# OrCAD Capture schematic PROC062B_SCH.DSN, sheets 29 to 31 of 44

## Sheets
29 28. MIPI 60 PIN CONNECTOR: size C; title: MIPI 60 PIN CONNECTOR
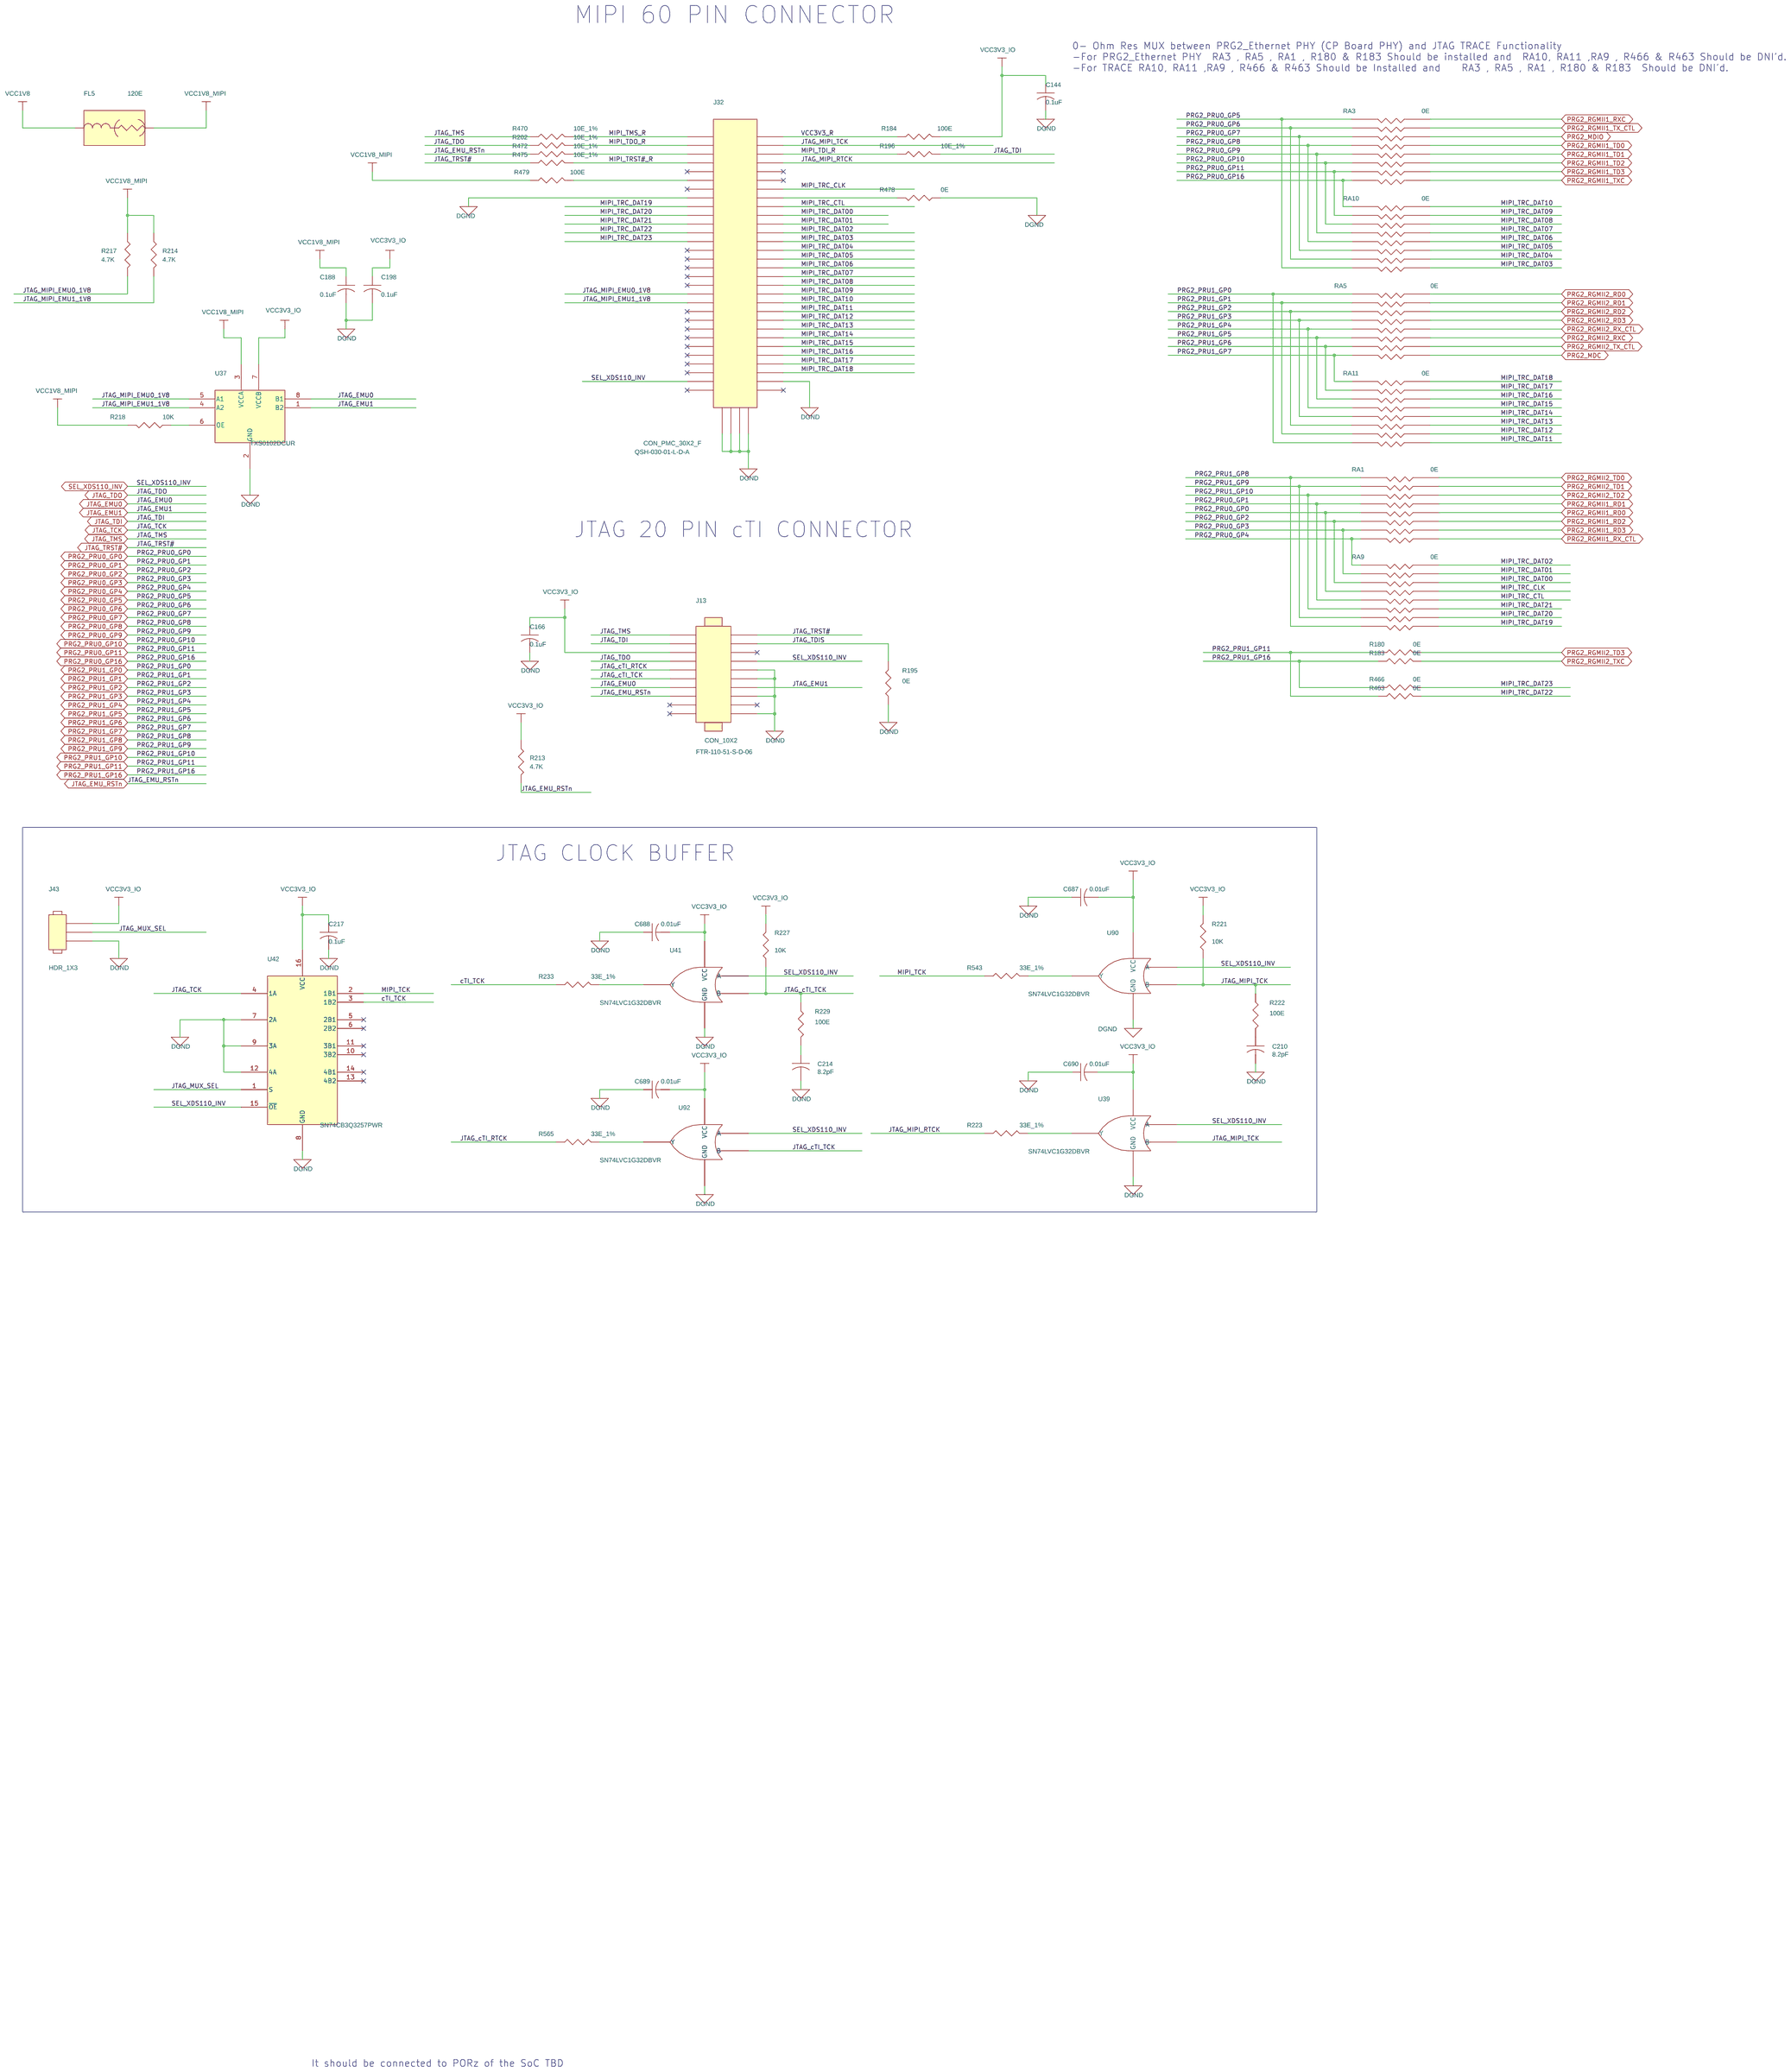
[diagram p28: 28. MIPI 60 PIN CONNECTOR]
30 29. USB2.0_INTERFACE: size C; title: USB 2.0 INTERFACE
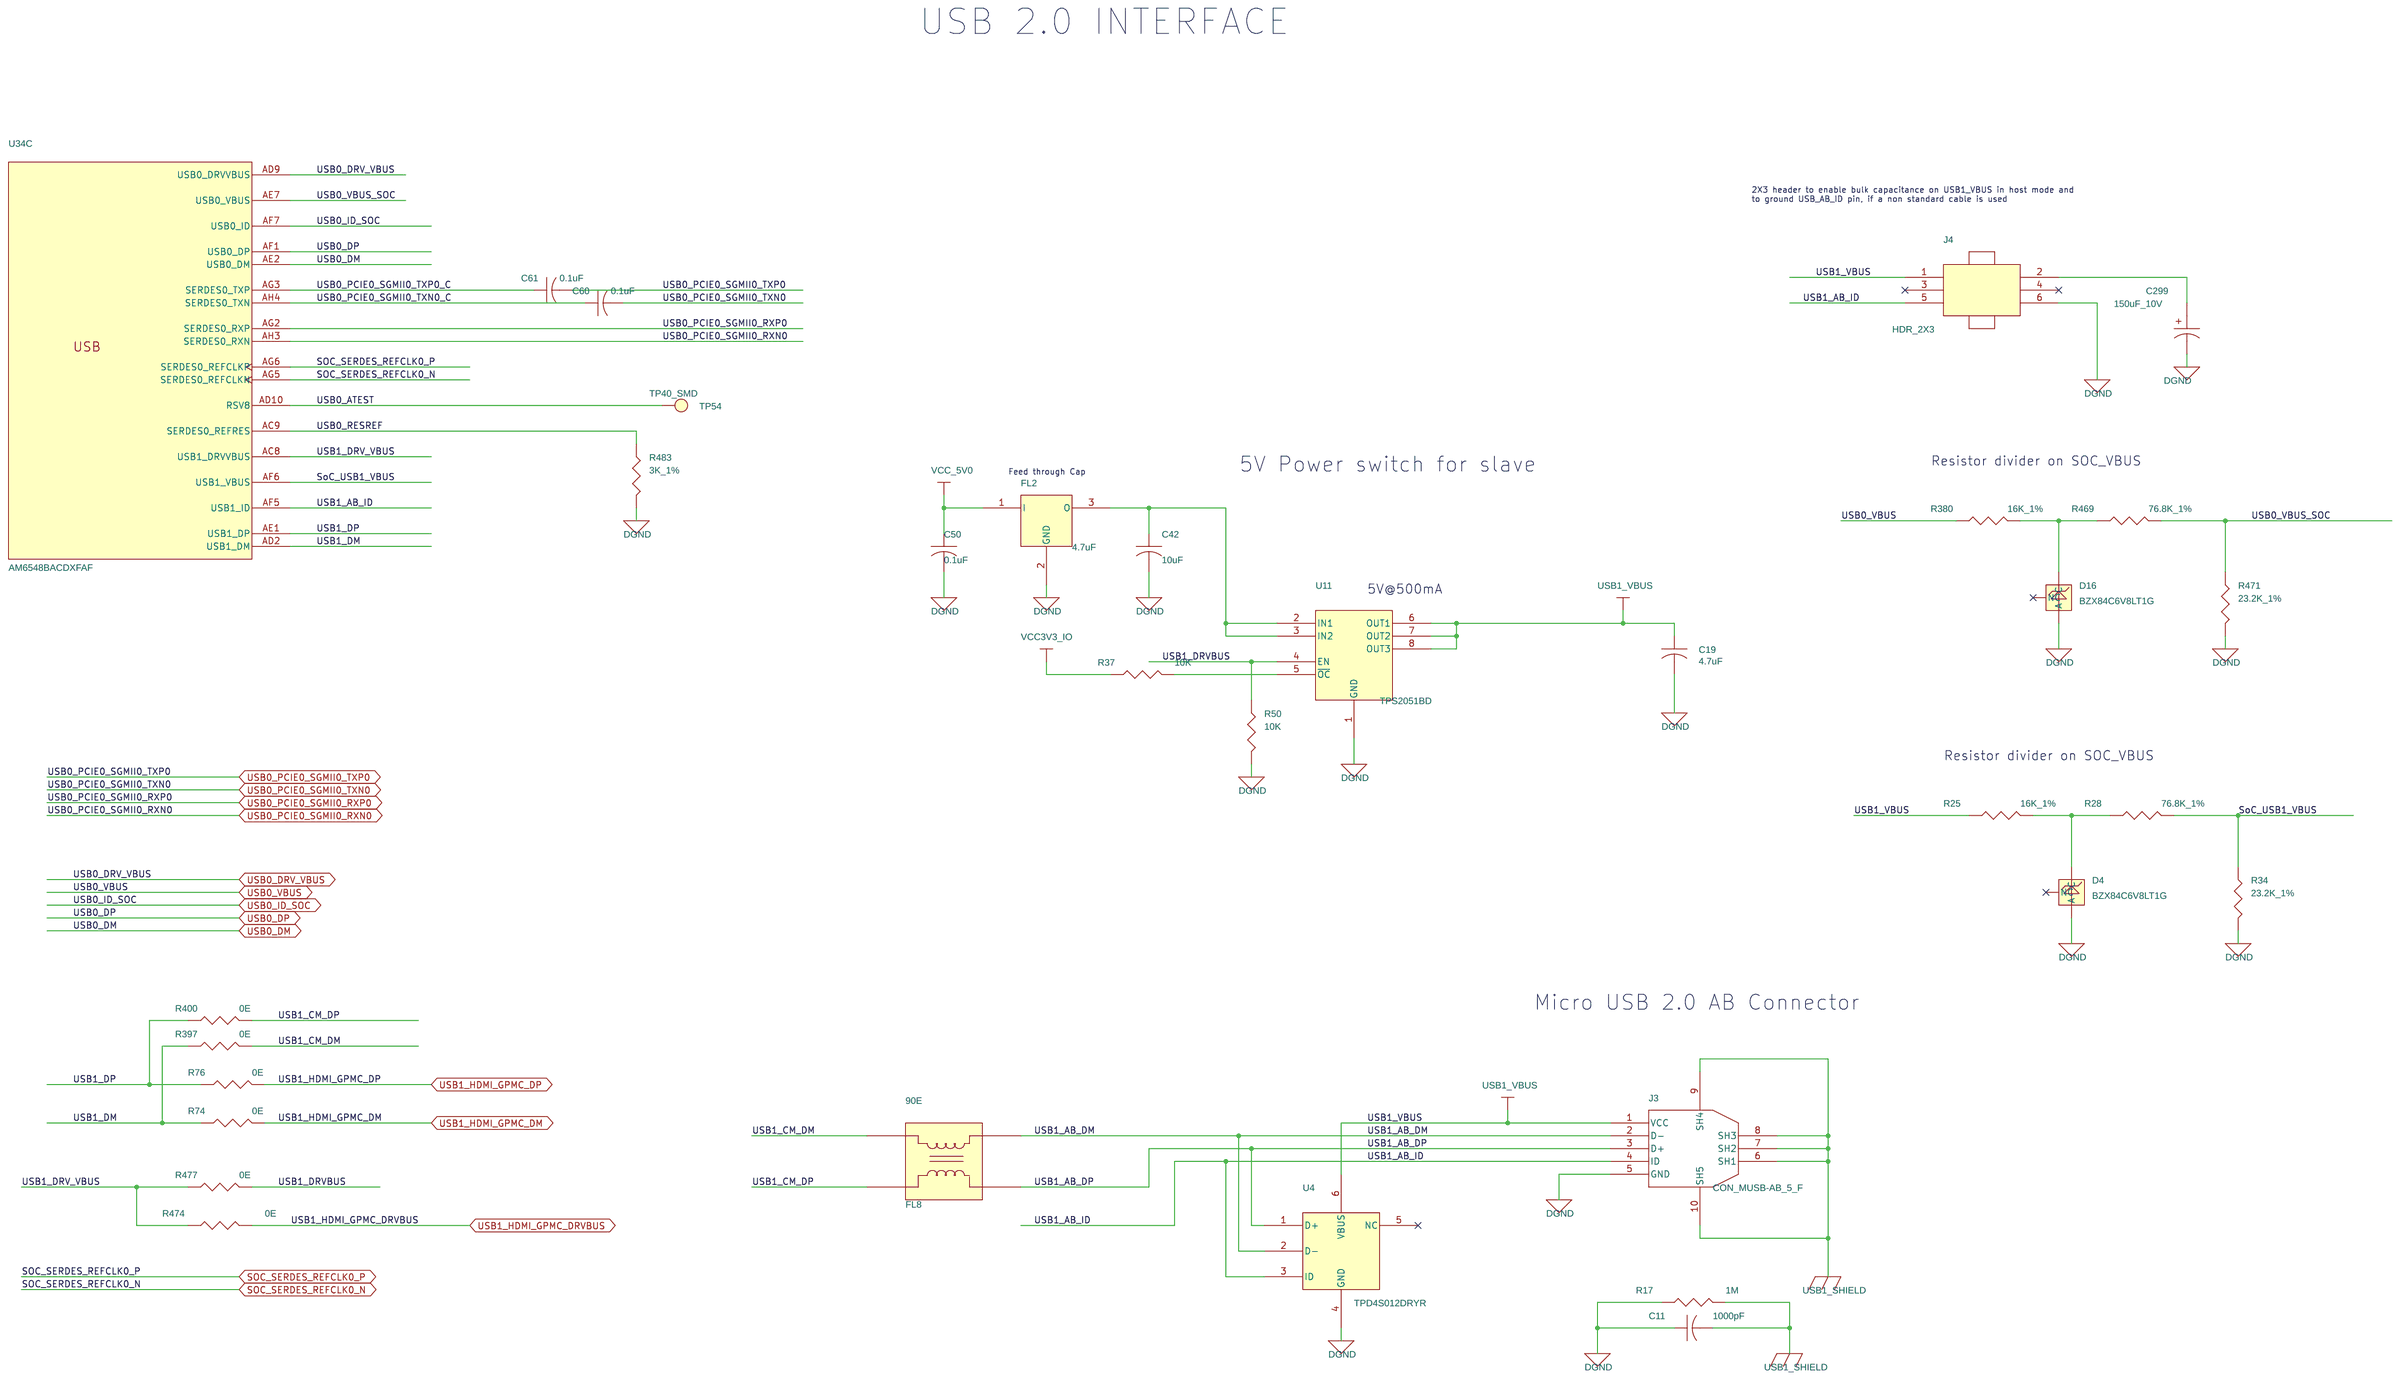
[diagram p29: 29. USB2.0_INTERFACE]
31 30. FT4232 LEVEL TRANSLATOR: size C; title: FT4232 LEVEL TRANSLATOR
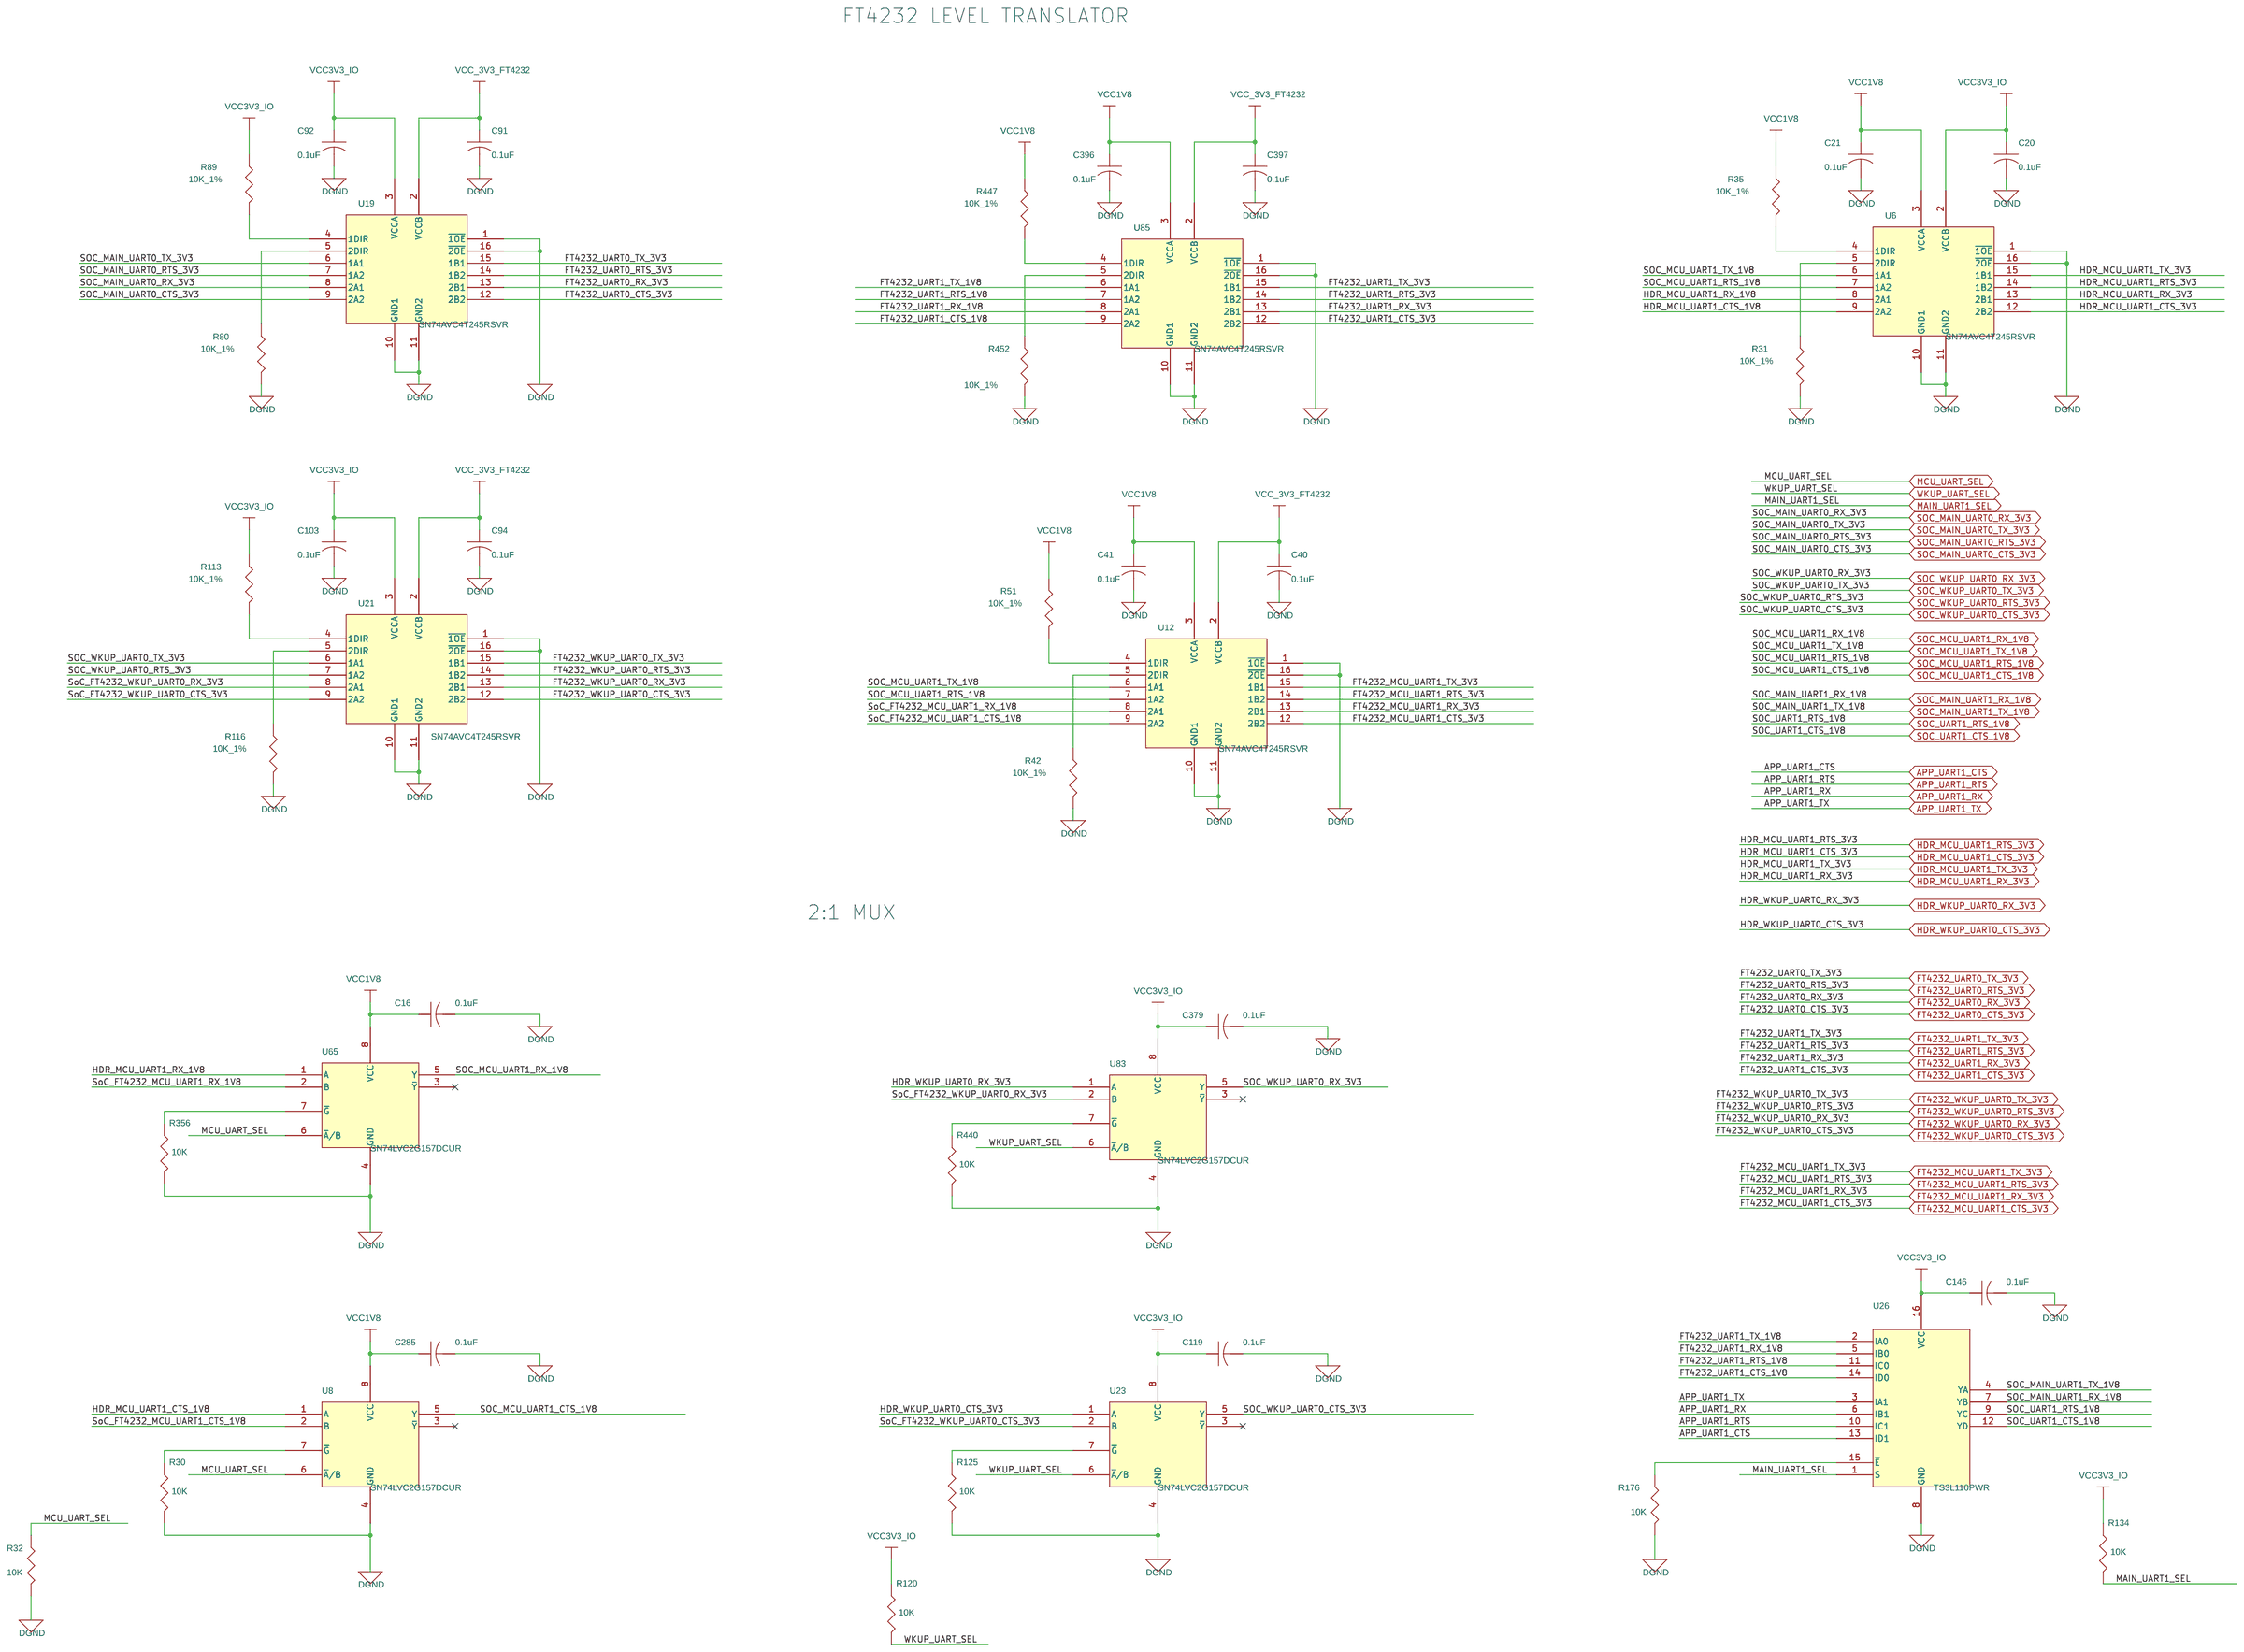
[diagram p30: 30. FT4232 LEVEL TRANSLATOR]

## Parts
sheet 16. DDR4 ECC & TERMINATIONS
U34  AM6548BACDXFAF  [BGA784_31-49_910X910_1-7]  (sections A,B,C,D,E,F,G,H,I,J,K,L,M,N,O,P,Q,R,S)
sheet 28. MIPI 60 PIN CONNECTOR
C144  0.1uF  [CAP0201_0-5]
C166  0.1uF  [CAP0201_0-5]
C188  0.1uF  [CAP0201_0-5]
C198  0.1uF  [CAP0201_0-5]
C210  8.2pF  [CAP0402_0-75]
C214  8.2pF  [CAP0402_0-75]
C217  0.1uF  [CAP0201_0-5]
C687  0.01uF  [CAP0201_0-5]
C688  0.01uF  [CAP0201_0-5]
C689  0.01uF  [CAP0201_0-5]
C690  0.01uF  [CAP0201_0-5]
FL5  120E  [EMIFIL_BLM15A_0402_0-6]
J13  CON_10X2  [CON_10X2_FTR-110-51-S-D_P_S_S]
J32  CON_PMC_30X2_F  [CON_PMC30X2_QSH-030-01-L_S_S_S]
J43  HDR_1X3  [HDR_3X1_100_S_T]
R180  0E  [RES0402_0-5]
R183  0E  [RES0402_0-5]
R184  100E  [RES0402_0-5]
R195  0E  [RES0402_0-5]
R196  10E_1%  [RES0402_0-5]
R202  10E_1%  [RES0402_0-5]
R213  4.7K  [RES0402]
R214  4.7K  [RES0402]
R217  4.7K  [RES0402]
R218  10K  [RES0402_0-5]
R221  10K  [RES0402_0-5]
R222  100E  [RES0402_0-5]
R223  33E_1%  [RES0402_0-5]
R227  10K  [RES0402_0-5]
R229  100E  [RES0402_0-5]
R233  33E_1%  [RES0402_0-5]
R463  0E  [RES0402_0-5]
R466  0E  [RES0402_0-5]
R470  10E_1%  [RES0402_0-5]
R472  10E_1%  [RES0402_0-5]
R475  10E_1%  [RES0402_0-5]
R478  0E  [RES0402_0-5]
R479  100E  [RES0402_0-5]
R543  33E_1%  [RES0402_0-5]
R565  33E_1%  [RES0402_0-5]
RA1  0E  [RESA_EXB2HV_0602-8_0-6]
RA3  0E  [RESA_EXB2HV_0602-8_0-6]
RA5  0E  [RESA_EXB2HV_0602-8_0-6]
RA9  0E  [RESA_0402-8]
RA10  0E  [RESA_0402-8]
RA11  0E  [RESA_0402-8]
U37  TXS0102DCUR  [VSSOP8_19-68_85X95_0-9]
U39  SN74LVC1G32DBVR  [SOT23-5_1-5]
U41  SN74LVC1G32DBVR  [SOT23-5_1-5]
U42  SN74CB3Q3257PWR  [TSSOP16_25-59_205X180]
U90  SN74LVC1G32DBVR  [SOT23-5_1-5]
U92  SN74LVC1G32DBVR  [SOT23-5_1-5]
sheet 29. USB2.0_INTERFACE
C11  1000pF  [CAP1206]
C19  4.7uF  [CAP0402_0-75]
C42  10uF  [CAP0603_1]
C50  0.1uF  [CAP0201_0-5]
C60  0.1uF  [CAP0402_0-75]
C61  0.1uF  [CAP0402_0-75]
C299  150uF_10V  [CAPT7343D_3-25]
D4  BZX84C6V8LT1G  [SOT23-123_1-2]
D16  BZX84C6V8LT1G  [SOT23-123_1-2]
FL2  4.7uF  [EMIFIL_NFM21P_0805_1]
FL8  90E  [IND4_ACM2012_90X50_SMD_1-3]
J3  CON_MUSB-AB_5_F  [CON_USBAB5_475900001_S_R_S_3-1]
J4  HDR_2X3  [HDR_2X3_TSW-103-07-D_S_T_8-4]
R17  1M  [RES0603_0-75]
R25  16K_1%  [RES0402]
R28  76.8K_1%  [RES0402]
R34  23.2K_1%  [RES0402]
R37  10K  [RES0402_0-5]
R50  10K  [RES0402_0-5]
R74  0E  [RES0402_0-5]
R76  0E  [RES0402_0-5]
R380  16K_1%  [RES0402]
R397  0E  [RES0402_0-5]
R400  0E  [RES0402_0-5]
R469  76.8K_1%  [RES0402]
R471  23.2K_1%  [RES0402]
R474  0E  [RES0402_0-5]
R477  0E  [RES0402_0-5]
R483  3K_1%  [RES0402_0-5]
TP54  TP40_SMD  [TP40_SMD]
U4  TPD4S012DRYR  [SON6_19-68_40X60_PB_0-6]
U11  TPS2051BD  [SOIC8_1-8]
sheet 30. FT4232 LEVEL TRANSLATOR
C16  0.1uF  [CAP0201_0-5]
C20  0.1uF  [CAP0201_0-5]
C21  0.1uF  [CAP0201_0-5]
C40  0.1uF  [CAP0201_0-5]
C41  0.1uF  [CAP0201_0-5]
C91  0.1uF  [CAP0201_0-5]
C92  0.1uF  [CAP0201_0-5]
C94  0.1uF  [CAP0201_0-5]
C103  0.1uF  [CAP0201_0-5]
C119  0.1uF  [CAP0201_0-5]
C146  0.1uF  [CAP0201_0-5]
C285  0.1uF  [CAP0201_0-5]
C379  0.1uF  [CAP0201_0-5]
C396  0.1uF  [CAP0201_0-5]
C397  0.1uF  [CAP0201_0-5]
R30  10K  [RES0402_0-5]
R31  10K_1%  [RES0402_0-5]
R32  10K  [RES0402_0-5]
R35  10K_1%  [RES0402_0-5]
R42  10K_1%  [RES0402_0-5]
R51  10K_1%  [RES0402_0-5]
R80  10K_1%  [RES0402_0-5]
R89  10K_1%  [RES0402_0-5]
R113  10K_1%  [RES0402_0-5]
R116  10K_1%  [RES0402_0-5]
R120  10K  [RES0402_0-5]
R125  10K  [RES0402_0-5]
R134  10K  [RES0402_0-5]
R176  10K  [RES0402_0-5]
R356  10K  [RES0402_0-5]
R440  10K  [RES0402_0-5]
R447  10K_1%  [RES0402_0-5]
R452  10K_1%  [RES0402_0-5]
U6  SN74AVC4T245RSVR  [UQFN16_15-74_105X75_0-6]
U8  SN74LVC2G157DCUR  [VSSOP8_19-68_85X95_0-9]
U12  SN74AVC4T245RSVR  [UQFN16_15-74_105X75_0-6]
U19  SN74AVC4T245RSVR  [UQFN16_15-74_105X75_0-6]
U21  SN74AVC4T245RSVR  [UQFN16_15-74_105X75_0-6]
U23  SN74LVC2G157DCUR  [VSSOP8_19-68_85X95_0-9]
U26  TS3L110PWR  [TSSOP16_25-59_205X180]
U65  SN74LVC2G157DCUR  [VSSOP8_19-68_85X95_0-9]
U83  SN74LVC2G157DCUR  [VSSOP8_19-68_85X95_0-9]
U85  SN74AVC4T245RSVR  [UQFN16_15-74_105X75_0-6]

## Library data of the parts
U34 = AM654X_BGA784: IC AM65X MICRO CONTROLLER UNIT BGA784; Chkd/date: ALVY/010721; Crtd /date: MANIRAJA/010721; Custom_Duty: 15%; Customs_HS_Code: 85423100; Distributor_name: NA; Distributor_part_number: NA; Footprint Path: Y:\MIS_DATABASE\Library\ALTIUM_TOOL\PCB_FOOTPRINTS\Altium_Footprint_Lib.PcbLib; Height: 1.63MM; Library Path: Y:\MIS_DATABASE\Library\ALTIUM_TOOL\SCHEMATICS_PARTS\MS_MICROCONTROLLER_Library.schlib; Mfr_name: TEXAS INSTRUMENTS; Mistral Part No: 141221070001; Package: BGA784; Part_type: ICS\DIGITAL\MICROCONTROLLER; Project: TI_AM65X_CP; RoHS: NA; Temperature: NA; Tolerance: NA; Voltage: NA; Wattage: NA; Weight: NA; Datasheet: Y:\MIS_DATABASE\DATASHEETS\ICS\DIGITAL\MICROCONTROLLER\MAXWELLM4.PDF
C16 C20 C21 C40 C41 C50 C91 C92 C94 C103 C119 C144 C146 C166 C188 C198 C217 C285 C379 C396 C397 = CAP: CAP CERAMIC 0.1uF 16V 10% X5R 0201; Chkd/date: MANIRAJA/120218; Crtd /date: MANIRAJA/120218; Custom_Duty: 15%; Customs_HS_Code: 85322990; Distributor_name: DIGIKEY; Distributor_part_number: 490-16742-1-ND; Height: 0.33MM; Mfr_name: MURATA; Mfr_part_number: GRM033R61C104KE84J; Mistral Part No: 120009030072-R; Package: 0201; Part_type: CAPACITORS\CERAMIC; Project: TI_MAXIE_CPB; RoHS: RoHS; Temperature: -55°C+85°C; Tolerance: 10%; Voltage: 16V; Wattage: NA; Weight: 0.33mg; Datasheet: Y:\MIS_DATABASE\DATASHEETS\CAPACITORS\GRM033R61C104KE84.PDF
C210 C214 = CAP: CAP CERAMIC 8.2pF 50V 0.5pF C0G(NP0) 0402; Chkd/date: MANIRAJA/240118; Crtd /date: MANIRAJA/240118; Custom_Duty: 15%; Customs_HS_Code: 85322990; Distributor_name: DIGIKEY; Distributor_part_number: GCM1555C1H8R2DA16D-ND; Height: 0.55MM; Mfr_name: MURATA; Mfr_part_number: GCM1555C1H8R2DA16D; Mistral Part No: 120018010017-R; Package: 0402; Part_type: CAPACITORS\CERAMIC; Project: TI_MAXIE_CPB; RoHS: RoHS; Temperature: -55°C+125°C; Tolerance: 0.5pF%; Voltage: 50V; Wattage: NA; Weight: 6mg; Datasheet: Y:\MIS_DATABASE\DATASHEETS\CAPACITORS\MURATA-GCM-SER.PDF
C687-C690 = CAP: CAP CERAMIC 0.01uF 25V 10% X5R 0201; Chkd/date: MANIRAJA/230118; Crtd /date: MANIRAJA/230118; Custom_Duty: 15%; Customs_HS_Code: 85322990; Distributor_name: DIGIKEY; Distributor_part_number: GRM033R61E103KA12J-ND; Height: 0.33MM; Mfr_name: MURATA; Mfr_part_number: GRM033R61E103KA12J; Mistral Part No: 120018010007-R; Package: 0201; Part_type: CAPACITORS\CERAMIC; Project: TI_MAXIE_CPB; RoHS: RoHS; Temperature: -55°C+85°C; Tolerance: 10%; Voltage: 25V; Wattage: NA; Weight: 0.33mg; Datasheet: Y:\MIS_DATABASE\DATASHEETS\CAPACITORS\GRM033R61E103KA12.PDF
FL5 = EMIFILTER_IND: FERRITE CHIP 120E 1.3A 0402; Chkd/date: VASANTHA/010117; Crtd /date: CHAITHANYA/150312; Custom_Duty: 24%; Customs_HS_Code: 85437099; Distributor_name: DIGIKEY; Distributor_part_number: 490-5203-1-ND; Footprint Path: Y:\MIS_DATABASE\Library\ALTIUM_TOOL\PCB_FOOTPRINTS\Altium_Footprint_Lib.PcbLib; Height: 0.55MM; Library Path: Y:\MIS_DATABASE\Library\ALTIUM_TOOL\SCHEMATICS_PARTS\MS_FILTER_Library.schlib; Mfr_name: MURATA; Mfr_part_number: BLM15PD121SN1; Mistral Part No: 130012030043-R; Package: 0402; Part_type: MISC\FILTER; Project: GEN_3-8; RoHS: RoHS; Temperature: -55°C+125°C; Tolerance: 25%; Voltage: NA; Wattage: NA; Weight: 0.65mg; Datasheet: Y:\MIS_DATABASE\DATASHEETS\DISCRETES\INDUCTORS\BLM18K-SERIES.PDF
J13 = CON_10X2: CON 10X2 1.27MM PITCH MALE SMD; Chkd/date: BAVISH/050911; Crtd /date: CHAITHANYA/050811; Custom_Duty: 24%; Customs_HS_Code: 85369090; Distributor_name: DIGIKEY; Distributor_part_number: FTR-110-51-S-D-06-ND; Height: 7.37MM; Mfr_name: SAMTEC; Mfr_part_number: FTR-110-51-S-D-06; Mistral Part No: 150011090001-R; Package: SMD; Part_type: CONNECTOR\MISCELLANEOUS; Project: GEMYC; RoHS: RoHS; Temperature: -55°C+105°C; Tolerance: NA; Voltage: NA; Wattage: NA; Weight: NA; Datasheet: Y:\MIS_DATABASE\DATASHEETS\CONNECTORS\FTR-SERIES1.PDF
J32 = CON_PMC_30X2_F: CON PMC 30X2 0.50MM PITCH FEMALE ST SMD; Chkd/date: MAZHAR/180208; Crtd /date: USMAN/051108; Custom_Duty: 24%; Customs_HS_Code: 85369090; Height: 3.25MM; Mfr_name: SAMTEC; Mfr_part_number: QSH-030-01-L-D-A; Mistral Part No: 150009030606; Package: SMD; Part_type: CONNECTOR\PMC; Project: KHAN_HSST; Datasheet: Y:\MIS_DATABASE\DATASHEETS\CONNECTORS\QSH.PDF
J43 = HEADER_3X1: HDR 1X3 2.54MM PITCH ST TH; Chkd/date: VASANTHA/290616; Crtd /date: VASANTHA/290616; Custom_Duty: 15%; Customs_HS_Code: 85322990; Distributor_name: DIGIKEY; Distributor_part_number: 609-3471-ND; Height: 8.58MM; Mfr_name: FCI; Mfr_part_number: 68001-403HLF; Mistral Part No: 150016060025-R; Package: THRU-HOLE; Part_type: CONNECTOR\HEADERS; Project: IKEYP; RoHS: RoHS; Temperature: -40°C+105°C; Tolerance: NA; Voltage: NA; Wattage: NA; Weight: NA; Datasheet: Y:\MIS_DATABASE\DATASHEETS\CONNECTORS\68000.PDF
R180 R183 R463 R466 = RESISTOR: RES 0E 1/16W 0402; Chkd/date: VASANTHA/201216; Crtd /date: MUDDU/190810; Custom_Duty: 15%; Customs_HS_Code: 85332119; Distributor_name: DIGIKEY; Distributor_part_number: 541-0.0JCT-ND; Footprint Path: Y:\MIS_DATABASE\Library\ALTIUM_TOOL\PCB_FOOTPRINTS\Altium_Footprint_Lib.PcbLib; Height: 0.40MM; Library Path: Y:\MIS_DATABASE\Library\ALTIUM_TOOL\SCHEMATICS_PARTS\MS_DISCRETE_Library.schlib; Mfr_name: VISHAY; Mfr_part_number: CRCW04020000Z0ED; Mistral Part No: 110010080019-P; Package: 0402; Part_type: RESISTORS\FIXED; Project: PB_BUGBASE; RoHS: Pb-Free; SIGNAL_MODEL: RES; Temperature: -55°C+155°C; Tolerance: NA; Voltage: NA; Wattage: 1/16W; Weight: 0.65g/1000pcs; Datasheet: Y:\MIS_DATABASE\DATASHEETS\RESISTORS\CRCW0603.PDF
R184 R222 R229 R479 = RESISTOR: RES 100E 1/16W 5% 0402; Chkd/date: MANIRAJA/230817; Crtd /date: MANIRAJA/230817; Custom_Duty: 15%; Customs_HS_Code: 85332119; Distributor_name: DIGIKEY; Distributor_part_number: 541-100JCT-ND; Height: 0.40MM; Mfr_name: VISHAY; Mfr_part_number: CRCW0402100RJNED; Mistral Part No: 110009030164-R; Package: 0402; Part_type: RESISTORS\FIXED; Project: TI_MAXIE_CPB; RoHS: RoHS; Temperature: -55°C+155°C; Tolerance: 5%; Voltage: NA; Wattage: 1/16W; Weight: 0.65mg; Datasheet: Y:\MIS_DATABASE\DATASHEETS\RESISTORS\CRCW0603.PDF
R74 R76 R195 R397 R400 R474 R477 R478 = RESISTOR: RES 0E 1/16W 0402; Chkd/date: VASANTHA/201216; Crtd /date: MUDDU/190810; Custom_Duty: 15%; Customs_HS_Code: 85332119; Distributor_name: DIGIKEY; Distributor_part_number: 541-0.0JCT-ND; Footprint Path: Y:\MIS_DATABASE\Library\ALTIUM_TOOL\PCB_FOOTPRINTS\Altium_Footprint_Lib.PcbLib; Height: 0.40MM; Library Path: Y:\MIS_DATABASE\Library\ALTIUM_TOOL\SCHEMATICS_PARTS\MS_DISCRETE_Library.schlib; Mfr_name: VISHAY; Mfr_part_number: CRCW04020000Z0ED; Mistral Part No: 110010080019-P; Package: 0402; Part_type: RESISTORS\FIXED; Project: PB_BUGBASE; RoHS: Pb-Free; Temperature: -55°C+155°C; Tolerance: NA; Voltage: NA; Wattage: 1/16W; Weight: 0.65g/1000pcs; Datasheet: Y:\MIS_DATABASE\DATASHEETS\RESISTORS\CRCW0603.PDF
R196 R202 R470 R472 R475 = RESISTOR: RES 10E 1/16W 1% 0402; Chkd/date: MANIRAJA/070218; Crtd /date: ALVY/070218; Custom_Duty: 15%; Customs_HS_Code: 85332119; Distributor_name: DIGIKEY; Distributor_part_number: 311-10.0LRCT-ND; Height: 0.40MM; Mfr_name: YAGEO AMERICA; Mfr_part_number: RC0402FR-0710RL; Mistral Part No: 110018020004-R; Package: 0402; Part_type: RESISTORS\FIXED; Project: TI_MAXIE_CPB; RoHS: RoHS; Temperature: -55°C+155°C; Tolerance: 1%; Voltage: NA; Wattage: 1/16W; Weight: 0.65mg; Datasheet: Y:\MIS_DATABASE\DATASHEETS\RESISTORS\YAGEO-RC0402.PDF
R213 R214 R217 = RESISTOR: RES 4.7K 1/16W 5% 0402; Chkd/date: VASANTHA/130516; Crtd /date: VASANTHA/130516; Custom_Duty: 15%; Customs_HS_Code: 85332119; Distributor_name: DIGIKEY; Distributor_part_number: 311-4.7KJRCT-ND; Height: 0.55MM; Mfr_name: YAGEO AMERICA; Mfr_part_number: RC0402JR-074K7L; Mistral Part No: 110009030792-R; Package: 0402; Part_type: RESISTORS\FIXED; Project: TMDXCSK368; RoHS: RoHS; Temperature: -55°C+155°C; Tolerance: 5%; Voltage: NA; Wattage: 1/16W; Weight: NA; Datasheet: Y:\MIS_DATABASE\DATASHEETS\RESISTORS\YAGEO-RC0402.PDF
R30 R32 R37 R50 R120 R125 R134 R176 R218 R221 R227 R356 R440 = RESISTOR: RES 10K 1/16W 5% 0402; Chkd/date: VASANTHA/061216; Crtd /date: MAZHAR/230805; Custom_Duty: 15%; Customs_HS_Code: 85332119; Distributor_name: DIGIKEY; Distributor_part_number: 311-10KJRCT-ND; Footprint Path: Y:\MIS_DATABASE\Library\ALTIUM_TOOL\PCB_FOOTPRINTS\Altium_Footprint_Lib.PcbLib; Height: 0.40MM; Library Path: Y:\MIS_DATABASE\Library\ALTIUM_TOOL\SCHEMATICS_PARTS\MS_DISCRETE_Library.schlib; Mfr_name: YAGEO AMERICA; Mfr_part_number: RC0402JR-0710KL; Mistral Part No: 110009030208-R; Package: 0402; Part_type: RESISTORS\FIXED; Project: HSE; RoHS: Pb-Free; Temperature: -55°C+155°C; Tolerance: 5%; Voltage: NA; Wattage: 1/16W; Weight: 0.65mg; Datasheet: Y:\MIS_DATABASE\DATASHEETS\RESISTORS\YAGEO-RC0402.PDF
R223 R233 R543 R565 = RESISTOR: RES 33E 1/16W 1% 0402; Chkd/date: VASANTHA/061216; Crtd /date: JEBRAN/171114; Custom_Duty: 15%; Customs_HS_Code: 85332119; Distributor_name: DIGIKEY; Distributor_part_number: P33.0LCT-ND; Height: 0.40MM; Mfr_name: PANASONIC-ECG; Mfr_part_number: ERJ-2RKF33R0X; Mistral Part No: 110014110006-R; Package: 0402; Part_type: RESISTORS\FIXED; Project: ZK BIOMETRIC; RoHS: RoHS; Temperature: -55°C+125°C; Tolerance: 1%; Voltage: NA; Wattage: 1/16W; Weight: 0.8g/1000pcs; Datasheet: Y:\MIS_DATABASE\DATASHEETS\RESISTORS\PAN-ERJSERIES.PDF
RA1 RA3 RA5 = RESARR_ISO8_0402: RES ARRAY 0E 1/16W JUMPER 0602-8; Chkd/date: SHREESHAIL/121205; Crtd /date: MAZHAR/300505; Custom_Duty: 15%; Customs_HS_Code: 85332119; Distributor_name: DIGIKEY; Distributor_part_number: Y1000CT-ND; Footprint Path: Y:\MIS_DATABASE\Library\ALTIUM_TOOL\PCB_FOOTPRINTS\Altium_Footprint_Lib.PcbLib; Height: 0.55MM; Library Path: Y:\MIS_DATABASE\Library\ALTIUM_TOOL\SCHEMATICS_PARTS\MS_DISCRETE_Library.schlib; Mfr_name: PANASONIC-ECG; Mfr_part_number: EXB-2HVR000V; Mistral Part No: 110009030004-R; Package: 0602-8; Part_type: RESISTORS\ARRAY; Project: V12SFP; RoHS: RoHS; SIGNAL_MODEL: RESA; Temperature: -55°C+125°C; Tolerance: NA; Voltage: NA; Wattage: 1/16W; Weight: 9mg; Datasheet: Y:\MIS_DATABASE\DATASHEETS\RESISTORS\EXB-18V.PDF
RA9-RA11 = RESARR_ISO8_0402: RES ARRAY 8 0E 0402; Chkd/date: SHREESHAIL/121205; Crtd /date: MAZHAR/300505; Distributor_name: DIGIKEY; Distributor_part_number: Y1000CT-ND; Height: 0.55MM; Mfr_name: PANASONIC-ECG; Mfr_part_number: EXB-2HVR000V; Mistral Part No: 110009030004-R; Package: 0402; Part_type: RESISTORS\ARRAY; Project: V12SFP; RoHS: RoHS; SIGNAL_MODEL: RESA; Datasheet: Y:\MIS_DATABASE\DATASHEETS\RESISTORS\EXB-2HV.PDF
U37 = TXS0102DCUR_VSSOP8: IC 2BIT BI-DIR VOLTAGE-LEVEL TRANSLATOR US8(VSSOP8); Chkd/date: MANIRAJA/130617; Crtd /date: SHREESHAIL/190108; Custom_Duty: 15%; Customs_HS_Code: 85423100; Distributor_name: DIGIKEY; Distributor_part_number: 296-21931-1-ND; Footprint Path: Y:\MIS_DATABASE\Library\ALTIUM_TOOL\PCB_FOOTPRINTS\Altium_Footprint_Lib.PcbLib; Height: 0.90MM; Library Path: Y:\MIS_DATABASE\Library\ALTIUM_TOOL\SCHEMATICS_PARTS\MS_MISCINTERFACE_Library.schlib; Mfr_name: TEXAS INSTRUMENTS; Mistral Part No: 141009030376-R; Package: US8; Part_type: ICS\INTERFACE\LEVEL TRANSLATOR; Project: SD_WATERLOO; RoHS: RoHS; Temperature: -40°C+85°C; Tolerance: NA; Voltage: NA; Wattage: NA; Weight: 9.6mg; Datasheet: Y:\MIS_DATABASE\DATASHEETS\ICS\INTERFACE\TXS0102.PDF
U39 U41 U90 U92 = SN74LVC1G32DBVR_SOT23-5: IC SINGAL 2 INPUT POSITIVE OR GATE SOT23-5; Chkd/date: MANIRAJA/051017; Crtd /date: MAZHAR/070806; Custom_Duty: 15%; Customs_HS_Code: 85423100; Distributor_name: DIGIKEY; Distributor_part_number: 296-9847-1-ND; Height: 1.45MM; Mfr_name: TEXAS INSTRUMENTS; Mistral Part No: 141009030236-R; Package: SOT23-5; Part_type: ICS\DIGITAL\GATES; Project: SVDO_RMB_MMA; RoHS: RoHS; Temperature: -40°C+85°C; Tolerance: NA; Voltage: NA; Wattage: NA; Weight: 6.3mg; Datasheet: Y:\MIS_DATABASE\DATASHEETS\ICS\DIGITAL\GATES\SN74LVC1G32.PDF
U42 = SN74CB3Q3257PWR_TSSOP16: IC 4BIT 1-OF-2 FET MULTIPLEXER/DEMULTIPLEXER TSSOP16; Chkd/date: SUHAS/251010; Crtd /date: USMAN/060109; Custom_Duty: 15%; Customs_HS_Code: 85423100; Distributor_name: DIGIKEY; Distributor_part_number: 296-19138-1-ND; Height: 1.20MM; Mfr_name: TEXAS INSTRUMENTS; Mistral Part No: 141009030117-R; Package: TSSOP16; Part_type: ICS\DIGITAL\COMBINATIONAL; Project: OMAP_EVM; RoHS: Sb/ Br FREE; Temperature: -40°C+85°C; Datasheet: Y:\MIS_DATABASE\DATASHEETS\ICS\DIGITAL\COMBINATIONAL\SN74CB3Q3257.PDF
C11 = CAP: CAP CERAMIC 1000pF 2KV 10% X7R 1206; Chkd/date: SHREESHAIL/291106; Crtd /date: MAZHAR/281106; Custom_Duty: 15%; Customs_HS_Code: 85322990; Distributor_name: DIGIKEY; Distributor_part_number: 478-2956-1-ND; Footprint Path: Y:\MIS_DATABASE\Library\ALTIUM_TOOL\PCB_FOOTPRINTS\Altium_Footprint_Lib.PcbLib; Height: 1.50MM; Library Path: Y:\MIS_DATABASE\Library\ALTIUM_TOOL\SCHEMATICS_PARTS\MS_DISCRETE_Library.schlib; Mfr_name: AVX CORPORATION; Mfr_part_number: 1206GC102KAT1A; Mistral Part No: 120009030147-R; Package: 1206; Part_type: CAPACITORS\CERAMIC; Project: ADR1B; RoHS: RoHS; Temperature: -55°C+125°C; Tolerance: 10%; Voltage: 2KV; Weight: NA; Datasheet: Y:\MIS_DATABASE\DATASHEETS\CAPACITORS\AVX_MLC.PDF
C19 = CAP: CAP CERAMIC 4.7uF 10V 20% X5R 0402; Chkd/date: MANIRAJA/230118; Crtd /date: MANIRAJA/230118; Custom_Duty: 15%; Customs_HS_Code: 85322990; Distributor_name: DIGIKEY; Distributor_part_number: 478-10791-1-ND; Height: 0.71MM; Mfr_name: AVX CORPORATION; Mfr_part_number: 0402ZD475MAT2A; Mistral Part No: 120012060002-R; Package: 0402; Part_type: CAPACITORS\CERAMIC; Project: TI_MAXIE_CPB; RoHS: RoHS; Temperature: -55°C+85°C; Tolerance: 20%; Voltage: 10V; Wattage: NA; Weight: 0.65mg; Datasheet: Y:\MIS_DATABASE\DATASHEETS\CAPACITORS\AVX_MLC.PDF
C42 = CAP: CAP CERAMIC 10uF 10V 10% X5R 0603; Chkd/date: MANIRAJA/230118; Crtd /date: MANIRAJA/230118; Custom_Duty: 15%; Customs_HS_Code: 85322990; Distributor_name: DIGIKEY; Distributor_part_number: 478-10766-1-ND; Height: 0.94MM; Mfr_name: AVX CORPORATION; Mfr_part_number: 0603ZD106KAT2A; Mistral Part No: 120010080001-R; Package: 0603; Part_type: CAPACITORS\CERAMIC; Project: TI_MAXIE_CPB; RoHS: RoHS; Temperature: -55°C+85°C; Tolerance: 10%; Voltage: 10V; Wattage: NA; Weight: 2mg; Datasheet: Y:\MIS_DATABASE\DATASHEETS\CAPACITORS\AVX_MLC.PDF
C60 C61 = CAP: CAP CERAMIC 0.1uF 16V 10% X7R 0402; Chkd/date: VASANTHA/300115; Crtd /date: USMAN/111012; Custom_Duty: 15%; Customs_HS_Code: 85322990; Distributor_name: MOUSER; Distributor_part_number: 581-530L104KT16T; Footprint Path: Y:\MIS_DATABASE\Library\ALTIUM_TOOL\PCB_FOOTPRINTS\Altium_Footprint_Lib.PcbLib; Height: 0.61MM; Library Path: Y:\MIS_DATABASE\Library\ALTIUM_TOOL\SCHEMATICS_PARTS\MS_DISCRETE_Library.schlib; Mfr_name: ATC; Mfr_part_number: ATC530L104KT16T; Mistral Part No: 120009030060-R; Package: 0402; Part_type: CAPACITORS\CERAMIC; Project: DTRM; Remarks: Distributor PART ADDED; RoHS: RoHS; Temperature: -55°C+125°C; Tolerance: 10%; Voltage: 16V; Wattage: NA; Weight: 0.65mg; Datasheet: Y:\MIS_DATABASE\DATASHEETS\CAPACITORS\ATC530.PDF
C299 = CAP_POL: CAP TANTALUM 150uF 10V 10% ESR 0.9E D7373; Chkd/date: MANIRAJA/240118; Crtd /date: MANIRAJA/240118; Custom_Duty: 15%; Customs_HS_Code: 85322990; Distributor_name: DIGIKEY; Distributor_part_number: 478-11241-1-ND; Height: 3.10MM; Mfr_name: AVX CORPORATION; Mfr_part_number: TAJD157K010TNJV; Mistral Part No: 120018010025-R; Package: D7373; Part_type: CAPACITORS\TANTALUM; Project: TI_MAXIE_CPB; RoHS: RoHS; Temperature: -55°C+125°C; Tolerance: 10%; Voltage: 10V; Wattage: NA; Weight: NA; Datasheet: Y:\MIS_DATABASE\DATASHEETS\CAPACITORS\TAJD156.PDF
D4 D16 = DIODE_ZENER_SOT23_13: DIODE ZENER 250mW 6.8V SOT23-123; Chkd/date: MANIRAJA/031017; Crtd /date: MANIRAJA/031017; Custom_Duty: 15%; Customs_HS_Code: 85412900; Distributor_name: DIGIKEY; Distributor_part_number: BZX84C6V8LT1GOSCT-ND; Height: 1.11MM; Mfr_name: ON SEMICONDUCTOR; Mistral Part No: 130017100002-R; Package: SOT23-123; Part_type: DIODE\ZENER; Project: TI_MAXIE_CPB; RoHS: RoHS; Temperature: -65°C+150°C; Tolerance: NA; Voltage: 6.8V; Wattage: NA; Weight: 8mg; Datasheet: Y:\MIS_DATABASE\DATASHEETS\DISCRETES\DIODES\BZX84XX.PDF
FL2 = EMI_FILTER: PASSIVE FILTER EMI 4.7uF 0805-3; Chkd/date: VASANTHA/191216; Crtd /date: USMAN/200409; Custom_Duty: 24%; Customs_HS_Code: 85437099; Distributor_name: NA; Distributor_part_number: NA; Height: 0.95MM; Mfr_name: MURATA; Mfr_part_number: NFM21PC475B1A3; Mistral Part No: 130009060011; Package: 0805; Part_type: MISC\FILTER; Project: AXON; Temperature: -40°C+85°C; Tolerance: NA; Voltage: NA; Wattage: NA; Weight: NA; Datasheet: Y:\MIS_DATABASE\DATASHEETS\DISCRETES\INDUCTORS\NFM21P.PDF
FL8 = EMIFILTER_ACM: PASSIVE FILTER COMMON MODE 90E 400mA SMD; Chkd/date: MANIRAJA/130218; Crtd /date: MAZHAR/270907; Custom_Duty: 24%; Customs_HS_Code: 85437099; Distributor_name: DIGIKEY; Distributor_part_number: 445-2207-1-ND; Height: 1.30MM; Mfr_name: TDK CORPORATION; Mfr_part_number: ACM2012-900-2P-T002; Mistral Part No: 130009030803-R; Package: SMD; Part_type: FILTER; Project: SMART VIEW_NVR; RoHS: RoHS; Temperature: -40°C+85°C; Tolerance: NA; Voltage: NA; Wattage: NA; Weight: 5.5mg; Datasheet: Y:\MIS_DATABASE\DATASHEETS\ICS\MISC\ACM2012-SER.PDF
J3 = CON_USB_MINI-AB_10: CON MICRO USB-AB TYPE 5POS FEMALE RT SMD; Chkd/date: VASANTHA/060117; Crtd /date: MAZHAR/290909; Custom_Duty: 24%; Customs_HS_Code: 85369090; Distributor_name: DIGIKEY; Distributor_part_number: WM17144CT-ND; Height: 3.10MM; Mfr_name: MOLEX; Mfr_part_number: 475900001; Mistral Part No: 150009090024-R; Package: SMD; Part_type: CONNECTOR\USB; Project: GOLDEN-I; RoHS: NA; Temperature: -30°C+85°C; Tolerance: NA; Voltage: NA; Wattage: NA; Weight: NA; Datasheet: Y:\MIS_DATABASE\DATASHEETS\CONNECTORS\475900.PDF
J4 = HEADER_3X2: CON HDR 2X3 2.54MM PITCH ST TH; Chkd/date: MANIRAJA/230118; Crtd /date: MANIRAJA/220118; Custom_Duty: 24%; Customs_HS_Code: 85369090; Distributor_name: DIGIKEY; Distributor_part_number: SAM1034-03-ND; Height: 8.38MM; Mfr_name: SAMTEC; Mfr_part_number: TSW-103-07-T-D; Mistral Part No: 150018010019-R; Package: THRU-HOLE; Part_type: CONNECTOR\HEADERS; Project: TI_MAXIE_CPB; RoHS: RoHS; Temperature: -55°C+105°C; Tolerance: NA; Voltage: NA; Wattage: NA; Weight: NA; Datasheet: Y:\MIS_DATABASE\DATASHEETS\CONNECTORS\TSW-MK.PDF
R17 = RESISTOR: RES 1M 1/10W 5% 0603; Chkd/date: VASANTHA/060217; Crtd /date: USMAN/111207; Custom_Duty: 15%; Customs_HS_Code: 85332119; Distributor_name: DIGIKEY; Distributor_part_number: P1.0MGCT-ND; Height: 0.55MM; Mfr_name: PANASONIC-ECG; Mfr_part_number: ERJ-3GEYJ105V; Mistral Part No: 110009030413-R; Package: 0603; Part_type: RESISTORS\FIXED; Project: BSN; RoHS: RoHS; Temperature: -55°C+155°C; Tolerance: 5%; Voltage: NA; Wattage: 1/10W; Weight: 2mg; Datasheet: Y:\MIS_DATABASE\DATASHEETS\RESISTORS\PAN-ERJ-3GE.PDF
R25 R380 = RESISTOR: RES 16K 1/16W 1% 0402; Chkd/date: VASANTHA/040616; Crtd /date: VASANTHA/040616; Custom_Duty: 15%; Customs_HS_Code: 85332119; Distributor_name: DIGIKEY; Distributor_part_number: RHM16KCDCT-ND; Height: 0.40MM; Mfr_name: ROHM; Mfr_part_number: MCR01MRTF1602; Mistral Part No: 110011030003-R; Package: 0402; Part_type: RESISTORS\FIXED; Project: TMDXCSKCC; RoHS: RoHS; Temperature: -55°C+155°C; Tolerance: 1%; Voltage: NA; Wattage: 1/16W; Weight: NA; Datasheet: Y:\MIS_DATABASE\DATASHEETS\RESISTORS\MCR01MRTF1211.PDF
R28 R469 = RESISTOR: RES 76.8K 1/16W 1% 0402; Chkd/date: VASANTHA/140616; Crtd /date: VASANTHA/140616; Custom_Duty: 15%; Customs_HS_Code: 85332119; Distributor_name: DIGIKEY; Distributor_part_number: YAG3230CT-ND; Height: 0.55MM; Mfr_name: YAGEO AMERICA; Mfr_part_number: RC0402FR-0776K8L; Mistral Part No: 110016060005-R; Package: 0402; Part_type: RESISTORS\FIXED; Project: TMDXCSKCC; RoHS: RoHS; Temperature: -55°C+155°C; Tolerance: 1%; Voltage: NA; Wattage: 1/16W; Weight: NA; Datasheet: Y:\MIS_DATABASE\DATASHEETS\RESISTORS\YAGEO-RC0402.PDF
R34 R471 = RESISTOR: RES 23.2K 1/16W 1% 0402; Chkd/date: JEBRAN/110815; Crtd /date: JEBRAN/110815; Cust_part_number: 4700-80154E; Custom_Duty: 15%; Customs_HS_Code: 85332119; Distributor_name: DIGIKEY; Distributor_part_number: 541-23.2KLCT-ND; Height: 0.40MM; Mfr_name: VISHAY; Mfr_part_number: CRCW040223K2FKED; Mistral Part No: 110015080017-R; Package: 0402; Part_type: RESISTORS\FIXED; Project: OCTASIC_3000; RoHS: RoHS; Temperature: -55°C+155°C; Tolerance: 1%; Voltage: NA; Wattage: 1/16W; Weight: NA; Datasheet: Y:\MIS_DATABASE\DATASHEETS\RESISTORS\CRCW0603.PDF
R483 = RESISTOR: RES 3K 1/16W 1% 0402; Chkd/date: MANIRAJA/101117; Crtd /date: MANIRAJA/101117; Custom_Duty: 15%; Customs_HS_Code: 85332119; Distributor_name: DIGIKEY; Distributor_part_number: 311-3KLRCT-ND; Height: 0.40MM; Mfr_name: YAGEO AMERICA; Mfr_part_number: RC0402FR-073KL; Mistral Part No: 110017110004-R; Package: 0402; Part_type: RESISTORS\FIXED; Project: TI_SVB_MAXWELL_DUT; RoHS: RoHS; Temperature: -55°C+155°C; Tolerance: 1%; Voltage: NA; Wattage: 1/16W; Weight: 0.65mg; Datasheet: Y:\MIS_DATABASE\DATASHEETS\RESISTORS\YAGEO.PDF
TP54 = TESTPOINT: TESTPOINT CIR 40 SMD; Chkd/date: MAZHAR/190505; Crtd /date: MAZHAR/190505; Distributor_name: NA; Distributor_part_number: NA; Footprint Path: Y:\MIS_DATABASE\Library\ALTIUM_TOOL\PCB_FOOTPRINTS\Altium_Footprint_Lib.PcbLib; Height: NA; Library Path: Y:\MIS_DATABASE\Library\ALTIUM_TOOL\SCHEMATICS_PARTS\MS_DISCRETE_Library.schlib; MECHANICAL 3D STEP FILE: NA; Mfr_name: LOCAL; Mistral Part No: 130009030933; Package: SMD; Project: RAINIER-3; RoHS: NA; Temperature: NA; Tolerance: NA; Voltage: NA; Wattage: NA; Weight: NA; Datasheet: NA
U4 = TPD4S012DRY_SON6: IC 4CH ESD SOLUTION SON6; Chkd/date: VASANTHA/060117; Crtd /date: BAVISH/190811; Custom_Duty: 15%; Customs_HS_Code: 85423100; Distributor_name: DIGIKEY; Distributor_part_number: 296-24244-1-ND; Height: 0.60MM; Mfr_name: TEXAS INSTRUMENTS; Mistral Part No: 141011080022-R; Package: SON6; Part_type: ICS\INTERFACE; Project: ACRO_DM3730; RoHS: RoHS; Temperature: -40°C+85°C; Tolerance: NA; Voltage: NA; Wattage: NA; Weight: NA; Datasheet: Y:\MIS_DATABASE\DATASHEETS\ICS\INTERFACE\TPD4S012.PDF
U11 = TPS2051BD_SOIC8: IC POWER DISTRIBUTION SWITCH SOIC8; Chkd/date: NAVEED/150714; Crtd /date: VASANTHA/190614; Custom_Duty: 15%; Customs_HS_Code: 85423100; Distributor_name: DIGIKEY; Distributor_part_number: 296-26911-5-ND; Footprint Path: Y:\MIS_DATABASE\Library\ALTIUM_TOOL\PCB_FOOTPRINTS\Altium_Footprint_Lib.PcbLib; Height: 1.75MM; Library Path: Y:\MIS_DATABASE\Library\ALTIUM_TOOL\SCHEMATICS_PARTS\MS_MISCPOWER_Library.schlib; Mfr_name: TEXAS INSTRUMENTS; Mistral Part No: 142014060011-R; Package: SOIC8; Part_type: ICS\POWER; Project: AEGIS_POM; RoHS: RoHS; Temperature: -40°C+125°C; Tolerance: NA; Voltage: NA; Wattage: NA; Weight: 72.6mg; Datasheet: Y:\MIS_DATABASE\DATASHEETS\MISC\REGULATORS\TPS2051BDBVR.PDF
R31 R35 R42 R51 R80 R89 R113 R116 R447 R452 = RESISTOR: RES 10K 1/16W 1% 0402; Chkd/date: VASANTHA/201216; Crtd /date: GEETHA/290506; Custom_Duty: 15%; Customs_HS_Code: 85332119; Distributor_name: DIGIKEY; Distributor_part_number: 311-10.0KLRTR-ND; Footprint Path: Y:\MIS_DATABASE\Library\ALTIUM_TOOL\PCB_FOOTPRINTS\Altium_Footprint_Lib.PcbLib; Height: 0.40MM; Library Path: Y:\MIS_DATABASE\Library\ALTIUM_TOOL\SCHEMATICS_PARTS\MS_DISCRETE_Library.schlib; Mfr_name: YAGEO AMERICA; Mfr_part_number: RC0402FR-0710KL; Mistral Part No: 110009030220-P; Package: 0402; Part_type: RESISTORS\FIXED; Project: VOCERA; RoHS: Pb-Free; Temperature: -55°C+155°C; Tolerance: 1%; Voltage: NA; Wattage: 1/16W; Weight: 0.65mg; Datasheet: Y:\MIS_DATABASE\DATASHEETS\RESISTORS\YAGEO-RC0402.PDF
U6 U12 U19 U21 U85 = SN74AVC4T245RSV_UQFN16: IC BUS TRANSCEIVER 4-BIT DUAL SUPPLY QFN16; Chkd/date: VASANTHA/221216; Crtd /date: BAVISH/190411; Custom_Duty: 15%; Customs_HS_Code: 85423100; Distributor_name: DIGIKEY; Distributor_part_number: 296-24366-1-ND; Height: 0.55MM; Mfr_name: TEXAS INSTRUMENTS; Mistral Part No: 141011040011-R; Package: QFN16; Part_type: ICS\DIGITAL\BUSTRANSCEIVER; Project: HMC; RoHS: RoHS; Temperature: -40°C+85°C; Tolerance: NA; Voltage: NA; Wattage: NA; Weight: NA; Datasheet: Y:\MIS_DATABASE\DATASHEETS\ICS\DIGITAL\BUSTRANSCEIVER\SN74AVC4T245XXXX.PDF
U8 U23 U65 U83 = SN74LVC2G157DCUR_VSSOP8: IC 2-LINE TO 1-LINE DATA SELECTOR MULTIPLEXER VSSOP8; Chkd/date: MANIRAJA/120917; Crtd /date: MANIRAJA/120917; Custom_Duty: 15%; Customs_HS_Code: 85423100; Distributor_name: DIGIKEY; Distributor_part_number: 296-12605-1-ND; Height: 0.90MM; Mfr_name: TEXAS INSTRUMENTS; Mistral Part No: 141017090014-R; Package: VSSOP8; Part_type: ICS\DIGITAL\COMBINATIONAL; Project: TI_MAXIE_CPB; RoHS: RoHS; Temperature: -40°C+85°C; Tolerance: NA; Voltage: NA; Wattage: NA; Weight: 9.6mg; Datasheet: Y:\MIS_DATABASE\DATASHEETS\ICS\DIGITAL\COMBINATIONAL\SN74LVC2G157.PDF
U26 = TS3L110PWG4_TSSOP16: IC QUAD SPDT SWITCH 8-4 CHANNEL MULTIPLEXER/DEMULTIPLEXER TSSOP16; Chkd/date: NAVEED/060115; Crtd /date: JEBRAN/051114; Custom_Duty: 15%; Customs_HS_Code: 85369090; Distributor_name: DIGIKEY; Distributor_part_number: TS3L110PWG4-ND; Footprint Path: Y:\MIS_DATABASE\Library\ALTIUM_TOOL\PCB_FOOTPRINTS\Altium_Footprint_Lib.PcbLib; Height: 1.20MM; Mfr_name: TEXAS INSTRUMENTS; Mistral Part No: 140114110002-R; Package: TSSOP16; Part_type: ICS\ANALOG\APPLICATION SPECIFIC; Project: GALILEO EVM; RoHS: RoHS; Temperature: -40°C+85°C; Tolerance: NA; Voltage: NA; Wattage: NA; Weight: NA; Datasheet: Y:\MIS_DATABASE\DATASHEETS\ICS\DIGITAL\COMBINATIONAL\TS3L110_SERIES.PDF

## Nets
DGND: C11.1 C16.2 C19.2 C20.2 C21.2 C40.2 C41.2 C42.2 C50.2 C91.2 C92.2 C94.2 C103.2 C119.2 C144.2 C146.2 C166.2 C188.2 C198.2 C210.2 C214.2 C217.2 C285.2 C299.2 C379.2 C396.2 C397.2 C687.1 C688.1 C689.1 C690.1 D4.1(A) D16.1(A) FL2.2(GND) J3.5(GND) J4.6 J13.10 J13.12 J13.16 J13.20 J32.16 J32.57 J32.61 J32.62 J32.63 J32.64 J43.3 R17.1 R30.2 R31.1 R32.2 R34.2 R42.1 R50.2 R80.1 R116.1 R125.2 R176.2 R195.1 R356.2 R440.2 R452.1 R471.2 R478.1 R483.2 U4.4(GND) U6.1(~{1OE}) U6.10(GND1) U6.11(GND2) U6.16(~{2OE}) U8.4(GND) U11.1(GND) U12.1(~{1OE}) U12.10(GND1) U12.11(GND2) U12.16(~{2OE}) U19.1(~{1OE}) U19.10(GND1) U19.11(GND2) U19.16(~{2OE}) U21.1(~{1OE}) U21.10(GND1) U21.11(GND2) U21.16(~{2OE}) U23.4(GND) U26.8(GND) U37.2(GND) U39.3(GND) U41.3(GND) U42.7(2A) U42.8(GND) U42.9(3A) U42.12(4A) U65.4(GND) U83.4(GND) U85.1(~{1OE}) U85.10(GND1) U85.11(GND2) U85.16(~{2OE}) U90.3(GND) U92.3(GND) ; also on sheet 11 12 13 14 15 16 17 18 19 20 21 22 23 24 25 26 27 28 32 33 34 35 36 37 38 39 40 41 42 43 44
VCC1V8: C16.1 C21.1 C41.1 C285.1 C396.1 FL5.1 R35.2 R51.2 R447.2 U6.3(VCCA) U8.8(VCC) U12.3(VCCA) U65.8(VCC) U85.3(VCCA) ; also on sheet 11 18 19 20 21 22 23 26 33 35 36 37 38 41 44
VCC1V8_MIPI: C188.1 FL5.2 R214.1 R217.1 R218.2 R479.1 U37.3(VCCA)
VCC3V3_IO: C20.1 C92.1 C103.1 C119.1 C144.1 C146.1 C166.1 C198.1 C217.1 C379.1 C687.2 C688.2 C689.2 C690.2 J13.5 J43.1 R37.1 R89.2 R113.2 R120.1 R134.1 R184.2 R213.1 R221.2 R227.2 U6.2(VCCB) U19.3(VCCA) U21.3(VCCA) U23.8(VCC) U26.16(VCC) U37.7(VCCB) U39.5(VCC) U41.5(VCC) U42.16(VCC) U83.8(VCC) U90.5(VCC) U92.5(VCC) ; also on sheet 11 18 19 20 21 22 23 24 25 26 28 33 34 35 36 37 38 39 41 42 43 44
VCC3V3_R: J32.1 R184.1
VCC_3V3_FT4232: C40.1 C91.1 C94.1 C397.1 U12.2(VCCB) U19.2(VCCB) U21.2(VCCB) U85.2(VCCB) ; also on sheet 32
VCC_5V0: C50.1 FL2.1(I) ; also on sheet 33 35 40 44
APP_UART1_CTS: U26.13(ID1) ; also on sheet 33
APP_UART1_RTS: U26.10(IC1) ; also on sheet 33
APP_UART1_RX: U26.6(IB1) ; also on sheet 33
APP_UART1_TX: U26.3(IA1) ; also on sheet 33
cTI_TCK: R233.1 U42.3(1B2)
FT4232_MCU_UART1_CTS_3V3: U12.12(2B2) ; also on sheet 32
FT4232_MCU_UART1_RTS_3V3: U12.14(1B2) ; also on sheet 32
FT4232_MCU_UART1_RX_3V3: U12.13(2B1) ; also on sheet 32
FT4232_MCU_UART1_TX_3V3: U12.15(1B1) ; also on sheet 32
FT4232_UART0_CTS_3V3: U19.12(2B2) ; also on sheet 32
FT4232_UART0_RTS_3V3: U19.14(1B2) ; also on sheet 32
FT4232_UART0_RX_3V3: U19.13(2B1) ; also on sheet 32
FT4232_UART0_TX_3V3: U19.15(1B1) ; also on sheet 32
FT4232_UART1_CTS_1V8: U26.14(ID0) U85.9(2A2)
FT4232_UART1_CTS_3V3: U85.12(2B2) ; also on sheet 32
FT4232_UART1_RTS_1V8: U26.11(IC0) U85.7(1A2)
FT4232_UART1_RTS_3V3: U85.14(1B2) ; also on sheet 32
FT4232_UART1_RX_1V8: U26.5(IB0) U85.8(2A1)
FT4232_UART1_RX_3V3: U85.13(2B1) ; also on sheet 32
FT4232_UART1_TX_1V8: U26.2(IA0) U85.6(1A1)
FT4232_UART1_TX_3V3: U85.15(1B1) ; also on sheet 32
FT4232_WKUP_UART0_CTS_3V3: U21.12(2B2) ; also on sheet 32
FT4232_WKUP_UART0_RTS_3V3: U21.14(1B2) ; also on sheet 32
FT4232_WKUP_UART0_RX_3V3: U21.13(2B1) ; also on sheet 32
FT4232_WKUP_UART0_TX_3V3: U21.15(1B1) ; also on sheet 32
HDR_MCU_UART1_CTS_1V8: U6.9(2A2) U8.1(A)
HDR_MCU_UART1_CTS_3V3: U6.12(2B2) ; also on sheet 38
HDR_MCU_UART1_RTS_3V3: U6.14(1B2) ; also on sheet 38
HDR_MCU_UART1_RX_1V8: U6.8(2A1) U65.1(A)
HDR_MCU_UART1_RX_3V3: U6.13(2B1) ; also on sheet 38
HDR_MCU_UART1_TX_3V3: U6.15(1B1) ; also on sheet 38
HDR_WKUP_UART0_CTS_3V3: U23.1(A) ; also on sheet 38
HDR_WKUP_UART0_RX_3V3: U83.1(A) ; also on sheet 38
JTAG_cTI_RTCK: J13.9 R565.1
JTAG_cTI_TCK: J13.11 R227.1 R229.1 U41.2(B) U92.2(B)
JTAG_EMU0: J13.13 U37.8(B1) ; also on sheet 28
JTAG_EMU1: J13.14 U37.1(B2) ; also on sheet 28
JTAG_EMU_RSTn: J13.15 R213.2 R472.1 ; also on sheet 39
JTAG_MIPI_EMU0_1V8: J32.38 R217.2 U37.5(A1)
JTAG_MIPI_EMU1_1V8: J32.40 R214.2 U37.4(A2)
JTAG_MIPI_RTCK: J32.7 R223.1
JTAG_MIPI_TCK: J32.3 R221.1 R222.1 U39.2(B) U90.2(B)
JTAG_MUX_SEL: J43.2 U42.1(S)
JTAG_TCK: U42.4(1A) ; also on sheet 28
JTAG_TDI: J13.3 R196.2 ; also on sheet 28
JTAG_TDIS: J13.4 R195.2
JTAG_TDO: J13.7 R202.1 ; also on sheet 28
JTAG_TMS: J13.1 R470.1 ; also on sheet 28
JTAG_TRST#: J13.2 R475.1 ; also on sheet 28
MAIN_UART1_SEL: R134.2 U26.1(S) ; also on sheet 37
MCU_UART_SEL: R32.1 U8.6(~{A}/B) U65.6(~{A}/B) ; also on sheet 37
MIPI_TCK: R543.1 U42.2(1B1)
MIPI_TDI_R: J32.5 R196.1
MIPI_TDO_R: J32.4 R202.2
MIPI_TMS_R: J32.2 R470.2
MIPI_TRC_CLK: J32.13 RA9.12
MIPI_TRC_CTL: J32.17 RA9.13
MIPI_TRC_DAT00: J32.19 RA9.11
MIPI_TRC_DAT01: J32.21 RA9.10
MIPI_TRC_DAT02: J32.23 RA9.9
MIPI_TRC_DAT03: J32.25 RA10.16
MIPI_TRC_DAT04: J32.27 RA10.15
MIPI_TRC_DAT05: J32.29 RA10.14
MIPI_TRC_DAT06: J32.31 RA10.13
MIPI_TRC_DAT07: J32.33 RA10.12
MIPI_TRC_DAT08: J32.35 RA10.11
MIPI_TRC_DAT09: J32.37 RA10.10
MIPI_TRC_DAT10: J32.39 RA10.9
MIPI_TRC_DAT11: J32.41 RA11.16
MIPI_TRC_DAT12: J32.43 RA11.15
MIPI_TRC_DAT13: J32.45 RA11.14
MIPI_TRC_DAT14: J32.47 RA11.13
MIPI_TRC_DAT15: J32.49 RA11.12
MIPI_TRC_DAT16: J32.51 RA11.11
MIPI_TRC_DAT17: J32.53 RA11.10
MIPI_TRC_DAT18: J32.55 RA11.9
MIPI_TRC_DAT19: J32.18 RA9.16
MIPI_TRC_DAT20: J32.20 RA9.15
MIPI_TRC_DAT21: J32.22 RA9.14
MIPI_TRC_DAT22: J32.24 R463.2
MIPI_TRC_DAT23: J32.26 R466.2
MIPI_TRST#_R: J32.8 R475.2
PRG2_MDC: RA5.16 ; also on sheet 21 22 35
PRG2_MDIO: RA3.11 ; also on sheet 21 22 35
PRG2_PRU0_GP0: RA1.4 RA9.5 ; also on sheet 21
PRG2_PRU0_GP1: RA1.5 RA9.4 ; also on sheet 21
PRG2_PRU0_GP2: RA1.3 RA9.6 ; also on sheet 21
PRG2_PRU0_GP3: RA1.2 RA9.7 ; also on sheet 21
PRG2_PRU0_GP4: RA1.1 RA9.8 ; also on sheet 21
PRG2_PRU0_GP5: RA3.8 RA10.1 ; also on sheet 21
PRG2_PRU0_GP6: RA3.7 RA10.2 ; also on sheet 21
PRG2_PRU0_GP7: RA3.6 RA10.3 ; also on sheet 21
PRG2_PRU0_GP8: RA3.5 RA10.4 ; also on sheet 21
PRG2_PRU0_GP9: RA3.4 RA10.5 ; also on sheet 21
PRG2_PRU0_GP10: RA3.3 RA10.6 ; also on sheet 21
PRG2_PRU0_GP11: RA3.2 RA10.7 ; also on sheet 21
PRG2_PRU0_GP16: RA3.1 RA10.8 ; also on sheet 21
PRG2_PRU1_GP0: RA5.8 RA11.1 ; also on sheet 21
PRG2_PRU1_GP1: RA5.7 RA11.2 ; also on sheet 21
PRG2_PRU1_GP2: RA5.6 RA11.3 ; also on sheet 21
PRG2_PRU1_GP3: RA5.5 RA11.4 ; also on sheet 21
PRG2_PRU1_GP4: RA5.4 RA11.5 ; also on sheet 21
PRG2_PRU1_GP5: RA5.3 RA11.6 ; also on sheet 21
PRG2_PRU1_GP6: RA5.2 RA11.7 ; also on sheet 21
PRG2_PRU1_GP7: RA5.1 RA11.8 ; also on sheet 21
PRG2_PRU1_GP8: RA1.8 RA9.1 ; also on sheet 21
PRG2_PRU1_GP9: RA1.7 RA9.2 ; also on sheet 21
PRG2_PRU1_GP10: RA1.6 RA9.3 ; also on sheet 21
PRG2_PRU1_GP11: R180.1 R463.1 ; also on sheet 21
PRG2_PRU1_GP16: R183.1 R466.1 ; also on sheet 21
PRG2_RGMII1_RD0: RA1.13 ; also on sheet 21
PRG2_RGMII1_RD1: RA1.12 ; also on sheet 21
PRG2_RGMII1_RD2: RA1.14 ; also on sheet 21
PRG2_RGMII1_RD3: RA1.15 ; also on sheet 21
PRG2_RGMII1_RX_CTL: RA1.16 ; also on sheet 21
PRG2_RGMII1_RXC: RA3.9 ; also on sheet 21
PRG2_RGMII1_TD0: RA3.12 ; also on sheet 21
PRG2_RGMII1_TD1: RA3.13 ; also on sheet 21
PRG2_RGMII1_TD2: RA3.14 ; also on sheet 21
PRG2_RGMII1_TD3: RA3.15 ; also on sheet 21
PRG2_RGMII1_TX_CTL: RA3.10 ; also on sheet 21
PRG2_RGMII1_TXC: RA3.16 ; also on sheet 21
PRG2_RGMII2_RD0: RA5.9 ; also on sheet 22
PRG2_RGMII2_RD1: RA5.10 ; also on sheet 22
PRG2_RGMII2_RD2: RA5.11 ; also on sheet 22
PRG2_RGMII2_RD3: RA5.12 ; also on sheet 22
PRG2_RGMII2_RX_CTL: RA5.13 ; also on sheet 22
PRG2_RGMII2_RXC: RA5.14 ; also on sheet 22
PRG2_RGMII2_TD0: RA1.9 ; also on sheet 22
PRG2_RGMII2_TD1: RA1.10 ; also on sheet 22
PRG2_RGMII2_TD2: RA1.11 ; also on sheet 22
PRG2_RGMII2_TD3: R180.2 ; also on sheet 22
PRG2_RGMII2_TX_CTL: RA5.15 ; also on sheet 22
PRG2_RGMII2_TXC: R183.2 ; also on sheet 22
SEL_XDS110_INV: J13.8 J32.58 U39.1(A) U41.1(A) U42.15(~{OE}) U90.1(A) U92.1(A) ; also on sheet 28
SoC_FT4232_MCU_UART1_CTS_1V8: U8.2(B) U12.9(2A2)
SoC_FT4232_MCU_UART1_RX_1V8: U12.8(2A1) U65.2(B)
SoC_FT4232_WKUP_UART0_CTS_3V3: U21.9(2A2) U23.2(B)
SoC_FT4232_WKUP_UART0_RX_3V3: U21.8(2A1) U83.2(B)
SOC_MAIN_UART0_CTS_3V3: U19.9(2A2) ; also on sheet 34
SOC_MAIN_UART0_RTS_3V3: U19.7(1A2) ; also on sheet 34
SOC_MAIN_UART0_RX_3V3: U19.8(2A1) ; also on sheet 34
SOC_MAIN_UART0_TX_3V3: U19.6(1A1) ; also on sheet 34
SOC_MAIN_UART1_RX_1V8: U26.7(YB) ; also on sheet 33
SOC_MAIN_UART1_TX_1V8: U26.4(YA) ; also on sheet 33
SOC_MCU_UART1_CTS_1V8: U8.5(Y) ; also on sheet 19
SOC_MCU_UART1_RTS_1V8: U6.7(1A2) U12.7(1A2) ; also on sheet 19
SOC_MCU_UART1_RX_1V8: U65.5(Y) ; also on sheet 19
SOC_MCU_UART1_TX_1V8: U6.6(1A1) U12.6(1A1) ; also on sheet 19
SOC_SERDES_REFCLK0_N: U34.AG5(SERDES0_REFCLKN) ; also on sheet 35
SOC_SERDES_REFCLK0_P: U34.AG6(SERDES0_REFCLKP) ; also on sheet 35
SOC_UART1_CTS_1V8: U26.12(YD) ; also on sheet 33
SOC_UART1_RTS_1V8: U26.9(YC) ; also on sheet 33
SoC_USB1_VBUS: R28.2 R34.1 U34.AF6(USB1_VBUS)
SOC_WKUP_UART0_CTS_3V3: U23.5(Y) ; also on sheet 34
SOC_WKUP_UART0_RTS_3V3: U21.7(1A2) ; also on sheet 34 38
SOC_WKUP_UART0_RX_3V3: U83.5(Y) ; also on sheet 34
SOC_WKUP_UART0_TX_3V3: U21.6(1A1) ; also on sheet 34 38
USB0_ATEST: TP54.1(TP) U34.AD10(RSV8)
USB0_DM: U34.AE2(USB0_DM) ; also on sheet 35
USB0_DP: U34.AF1(USB0_DP) ; also on sheet 35
USB0_DRV_VBUS: U34.AD9(USB0_DRVVBUS) ; also on sheet 35
USB0_ID_SOC: U34.AF7(USB0_ID) ; also on sheet 35
USB0_PCIE0_SGMII0_RXN0: U34.AH3(SERDES0_RXN) ; also on sheet 35
USB0_PCIE0_SGMII0_RXP0: U34.AG2(SERDES0_RXP) ; also on sheet 35
USB0_PCIE0_SGMII0_TXN0: C60.2 ; also on sheet 35
USB0_PCIE0_SGMII0_TXN0_C: C60.1 U34.AH4(SERDES0_TXN)
USB0_PCIE0_SGMII0_TXP0: C61.2 ; also on sheet 35
USB0_PCIE0_SGMII0_TXP0_C: C61.1 U34.AG3(SERDES0_TXP)
USB0_RESREF: R483.1 U34.AC9(SERDES0_REFRES)
USB0_VBUS: R380.1 ; also on sheet 35
USB0_VBUS_SOC: R469.2 R471.1 U34.AE7(USB0_VBUS)
USB1_AB_DM: FL8.4 J3.2(D-) U4.2(D-)
USB1_AB_DP: FL8.3 J3.3(D+) U4.1(D+)
USB1_AB_ID: J3.4(ID) J4.5 U4.3(ID) U34.AF5(USB1_ID)
USB1_CM_DM: FL8.1 R397.2
USB1_CM_DP: FL8.2 R400.2
USB1_DM: R74.2 R397.1 U34.AD2(USB1_DM)
USB1_DP: R76.2 R400.1 U34.AE1(USB1_DP)
USB1_DRV_VBUS: R474.2 R477.1 U34.AC8(USB1_DRVVBUS)
USB1_DRVBUS: R50.1 R477.2 U11.4(EN)
USB1_HDMI_GPMC_DM: R74.1 ; also on sheet 44
USB1_HDMI_GPMC_DP: R76.1 ; also on sheet 44
USB1_HDMI_GPMC_DRVBUS: R474.1 ; also on sheet 44
USB1_SHIELD: C11.2 J3.6(SH1) J3.7(SH2) J3.8(SH3) J3.9(SH4) J3.10(SH5) R17.2
USB1_VBUS: C19.1 J3.1(VCC) J4.1 R25.1 U4.6(VBUS) U11.6(OUT1) U11.7(OUT2) U11.8(OUT3)
WKUP_UART_SEL: R120.2 U23.6(~{A}/B) U83.6(~{A}/B) ; also on sheet 37
N16753626: J32.6 R472.2
N16753680: J32.15 R478.2
N16754334: J32.12 R479.2
N17368941: R356.1 U65.7(~{G})
N17368953: R440.1 U83.7(~{G})
N17372472: R452.2 U85.5(2DIR)
N17372478: R447.1 U85.4(1DIR)
N17372544: R80.2 U19.5(2DIR)
N17372552: R89.1 U19.4(1DIR)
N17372616: R116.2 U21.5(2DIR)
N17372624: R113.1 U21.4(1DIR)
N17372676: R42.2 U12.5(2DIR)
N17372684: R51.1 U12.4(1DIR)
N17839730: C299.1 J4.2
N18022426: R31.2 U6.5(2DIR)
N18022434: R35.1 U6.4(1DIR)
N18024163: R30.1 U8.7(~{G})
N18024634: R125.1 U23.7(~{G})
N18275385: R218.1 U37.6(OE)
N18276744: C214.1 R229.2
N18280417: R233.2 U41.4(Y)
N18280437: R565.2 U92.4(Y)
N18280477: R543.2 U90.4(Y)
N18280857: R223.2 U39.4(Y)
N18968753: C42.1 FL2.3(O) U11.2(IN1) U11.3(IN2)
N18968782: R37.2 U11.5(~{OC})
N18972035: R176.1 U26.15(~{E})
N19311901: D16.3(C) R380.2 R469.1
N19312123: D4.3(C) R25.2 R28.1
N23516088: C210.1 R222.2

Not connected (* = marked no-connect by the designer): D4 2(NC)*; D16 2(NC)*; J4 3* 4*; J13 6* 17* 18* 19*; J32 9* 10* 11* 14* 28* 30* 32* 34* 36* 42* 44* 46* 48* 50* 52* 54* 56* 59* 60*; U4 5(NC)*; U8 3(~{Y})*; U23 3(~{Y})*; U42 5(2B1)* 6(2B2)* 10(3B2)* 11(3B1)* 13(4B2)* 14(4B1)*; U65 3(~{Y})*; U83 3(~{Y})*

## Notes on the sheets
sheet 29
- MIPI 60 PIN CONNECTOR
- 0- Ohm Res MUX between PRG2_Ethernet PHY (CP Board PHY) and JTAG TRACE Functionality
  -For PRG2_Ethernet PHY  RA3 , RA5 , RA1 , R180 & R183 Should be installed and  RA10, RA11 ,RA9 , R466 & R463 Should be DNI'd.
  -For TRACE RA10, RA11 ,RA9 , R466 & R463 Should be Installed and    RA3 , RA5 , RA1 , R180 & R183  Should be DNI'd.
- JTAG 20 PIN cTI CONNECTOR
- JTAG CLOCK BUFFER
- It should be connected to PORz of the SoC TBD
sheet 30
- USB 2.0 INTERFACE
- 2X3 header to enable bulk capacitance on USB1_VBUS in host mode and
  to ground USB_AB_ID pin, if a non standard cable is used
- Feed through Cap
- 5V Power switch for slave
- Resistor divider on SOC_VBUS
- 5V@500mA
- Resistor divider on SOC_VBUS
- Micro USB 2.0 AB Connector
sheet 31
- FT4232 LEVEL TRANSLATOR
- 2:1 MUX
